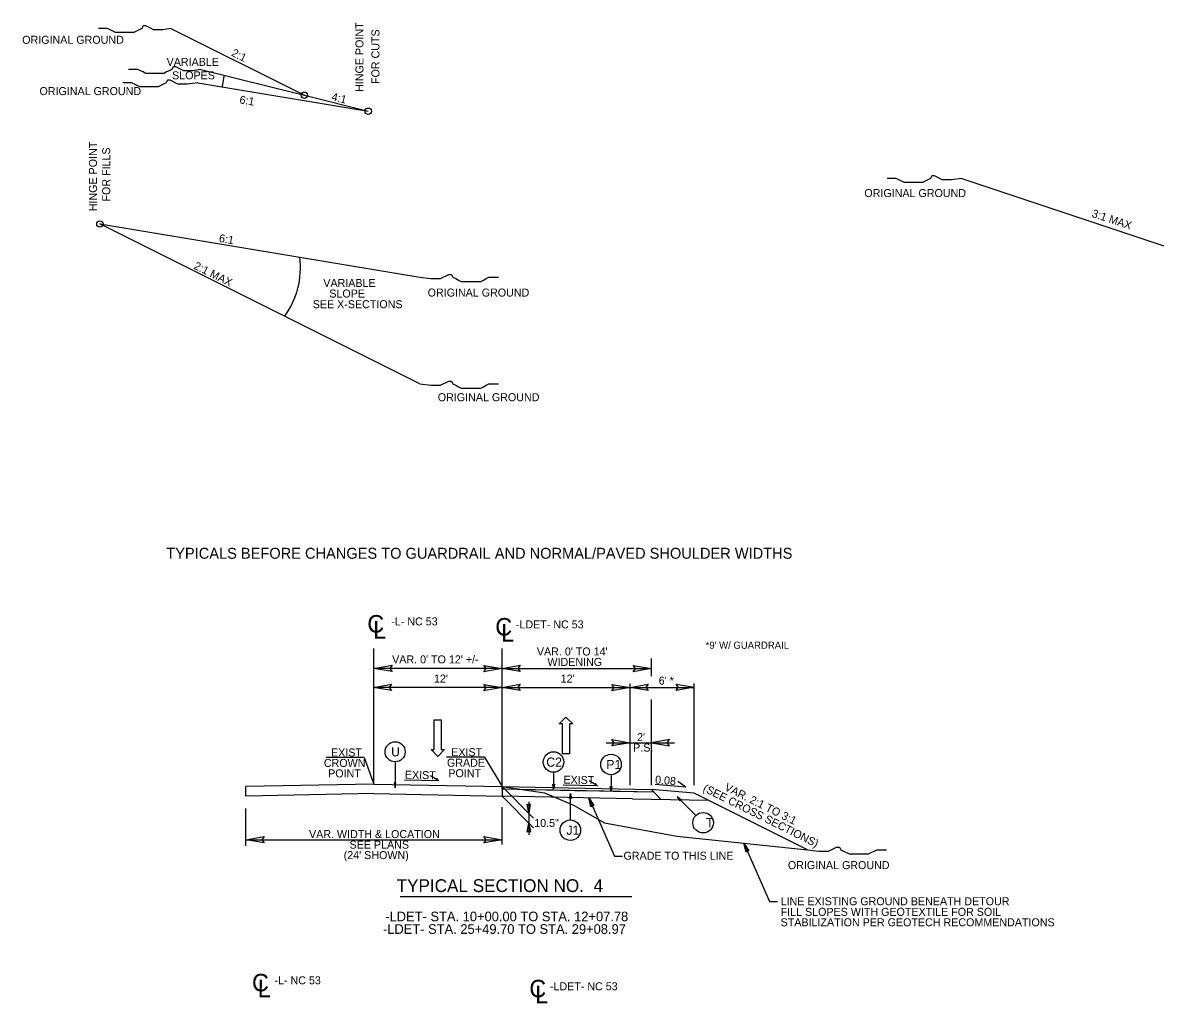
# Model space of a CAD drawing. Extents: x 1548135 to 1549339, y 868664 to 869085.
# Drawn here: x 1548321.3 to 1548427.5, y 868837.2 to 868929.2 of the extents above; entities that cross this region are included whole.
import ezdxf

# ---------------------------------------------------------------- set-up
doc = ezdxf.new("R2010")
doc.units = 0
for name, color, linetype in [('P_RDY_TC_Pvmt_Asphalt_Base_Course', 7, 'Continuous'), ('Prop Dimension', 7, 'Continuous'), ('Prop Terminator CELL', 7, 'Continuous'), ('Sheet_Data_Field_CELL', 7, 'Continuous'), ('Sheet_Plan', 7, 'Continuous'), ('Sheet_Title_Block_Text', 7, 'Continuous'), ('Typical Grade Point Symbol CELL', 7, 'Continuous'), ('Typical Hinge Slope Arterial CELL', 7, 'Continuous'), ('Typical Hinge Slope Interstate CELL', 7, 'Continuous'), ('Typical Pavement Slope Information CELL', 7, 'Continuous'), ('Typical Shoulder Slope CELL', 7, 'Continuous'), ('Typical Shoulder Slope Information CELL', 7, 'Continuous'), ('Typical Terminator CELL', 7, 'Continuous'), ('Typical Text Centerline CELL', 7, 'Continuous'), ('Typical Text General CELL', 7, 'Continuous'), ('Typical Text Grade Point CELL', 7, 'Continuous'), ('z - Construction', 7, 'Continuous')]:
    doc.layers.add(name, color=color, linetype=linetype)

msp = doc.modelspace()

# ---------------------------------------------------------------- linework, layer by layer
at = {"layer": 'P_RDY_TC_Pvmt_Asphalt_Base_Course'}
for points in [[(1548355.96, 868868.31), (1548354.27, 868868.6), (1548355.97, 868868.9), (1548355.75, 868868.6)], [(1548364.58, 868868.89), (1548366.27, 868868.6), (1548364.58, 868868.3), (1548364.79, 868868.6)], [(1548367.96, 868868.31), (1548366.27, 868868.6), (1548367.97, 868868.9), (1548367.75, 868868.6)], [(1548378.58, 868868.89), (1548380.27, 868868.6), (1548378.58, 868868.3), (1548378.79, 868868.6)], [(1548355.9, 868866.53), (1548354.21, 868866.82), (1548355.91, 868867.12), (1548355.69, 868866.82)], [(1548364.58, 868867.11), (1548366.27, 868866.82), (1548364.58, 868866.52), (1548364.79, 868866.82)], [(1548367.96, 868866.53), (1548366.27, 868866.82), (1548367.97, 868867.12), (1548367.75, 868866.82)], [(1548376.58, 868867.11), (1548378.27, 868866.82), (1548376.58, 868866.52), (1548376.79, 868866.82)], [(1548379.96, 868866.53), (1548378.27, 868866.82), (1548379.97, 868867.12), (1548379.75, 868866.82)], [(1548382.6, 868867.13), (1548384.28, 868866.84), (1548382.59, 868866.54), (1548382.8, 868866.84)], [(1548376.58, 868861.94), (1548378.27, 868861.64), (1548376.58, 868861.34), (1548376.79, 868861.64)], [(1548381.96, 868861.94), (1548380.27, 868861.64), (1548381.97, 868861.34), (1548381.75, 868861.64)], [(1548343.96, 868852.26), (1548342.27, 868852.55), (1548343.97, 868852.85), (1548343.75, 868852.55)], [(1548364.58, 868852.84), (1548366.27, 868852.55), (1548364.58, 868852.25), (1548364.79, 868852.55)]]:
    msp.add_lwpolyline(points, close=True, dxfattribs=at)
at = {"layer": 'Prop Dimension'}
for p, q in [((1548358.56, 868895.28), (1548328.57, 868910.28)), ((1548394.92, 868851.6), (1548384.28, 868856.92))]:
    msp.add_line(p, q, dxfattribs=at)
for points in [[(1548358.56, 868905.28), (1548359.6, 868905.15), (1548359.86, 868905.15), (1548360.25, 868905.15), (1548360.51, 868905.15), (1548360.77, 868905.28), (1548361.03, 868905.41), (1548361.29, 868905.54), (1548361.54, 868905.54), (1548361.67, 868905.28), (1548361.93, 868905.15), (1548362.19, 868905.02), (1548362.45, 868904.89), (1548362.71, 868904.89), (1548362.97, 868904.89), (1548363.23, 868904.89), (1548363.49, 868904.89), (1548363.75, 868904.89), (1548364.01, 868904.89), (1548364.27, 868904.89), (1548364.53, 868905.02), (1548364.79, 868905.15), (1548365.05, 868905.28), (1548365.44, 868905.28), (1548365.69, 868905.28), (1548365.95, 868905.28)], [(1548358.56, 868895.28), (1548359.6, 868895.15), (1548359.86, 868895.15), (1548360.25, 868895.15), (1548360.51, 868895.15), (1548360.77, 868895.28), (1548361.03, 868895.41), (1548361.29, 868895.54), (1548361.54, 868895.54), (1548361.67, 868895.28), (1548361.93, 868895.15), (1548362.19, 868895.02), (1548362.45, 868894.89), (1548362.71, 868894.89), (1548362.97, 868894.89), (1548363.23, 868894.89), (1548363.49, 868894.89), (1548363.75, 868894.89), (1548364.01, 868894.89), (1548364.27, 868894.89), (1548364.53, 868895.02), (1548364.79, 868895.15), (1548365.05, 868895.28), (1548365.44, 868895.28), (1548365.69, 868895.28), (1548365.95, 868895.28)], [(1548394.92, 868851.6), (1548395.96, 868851.47), (1548396.22, 868851.47), (1548396.61, 868851.47), (1548396.87, 868851.47), (1548397.13, 868851.6), (1548397.39, 868851.73), (1548397.64, 868851.86), (1548397.9, 868851.86), (1548398.03, 868851.6), (1548398.29, 868851.47), (1548398.55, 868851.34), (1548398.81, 868851.21), (1548399.07, 868851.21), (1548399.33, 868851.21), (1548399.59, 868851.21), (1548399.85, 868851.21), (1548400.11, 868851.21), (1548400.37, 868851.21), (1548400.63, 868851.21), (1548400.89, 868851.34), (1548401.15, 868851.47), (1548401.41, 868851.6), (1548401.8, 868851.6), (1548402.05, 868851.6), (1548402.31, 868851.6)]]:
    msp.add_lwpolyline(points, dxfattribs=at)
at = {"layer": 'Prop Terminator CELL'}
msp.add_lwpolyline([(1548366.27, 868857.53), (1548380.27, 868857.24), (1548380.52, 868857), (1548376.7, 868857.07), (1548375.4, 868857.1), (1548373.11, 868857.14), (1548366.27, 868857.28), (1548366.27, 868857.28)], close=True, dxfattribs=at)
at = {"layer": 'Sheet_Data_Field_CELL'}
for p, q in [((1548335.22, 868928.61), (1548347.74, 868922.35)), ((1548338.04, 868924.77), (1548347.74, 868922.35)), ((1548337.74, 868923.52), (1548353.73, 868920.85)), ((1548347.74, 868922.35), (1548353.73, 868920.85)), ((1548409.39, 868914.54), (1548438.24, 868904.93)), ((1548328.57, 868910.28), (1548358.56, 868905.28))]:
    msp.add_line(p, q, dxfattribs=at)
for points in [[(1548335.22, 868928.61), (1548334.48, 868928.49), (1548334.23, 868928.49), (1548333.86, 868928.49), (1548333.61, 868928.49), (1548333.37, 868928.61), (1548333.12, 868928.73), (1548332.87, 868928.86), (1548332.63, 868928.86), (1548332.5, 868928.61), (1548332.26, 868928.49), (1548332.01, 868928.36), (1548331.77, 868928.24), (1548331.52, 868928.24), (1548331.27, 868928.24), (1548331.03, 868928.24), (1548330.78, 868928.24), (1548330.53, 868928.24), (1548330.29, 868928.24), (1548330.04, 868928.24), (1548329.79, 868928.36), (1548329.55, 868928.49), (1548329.3, 868928.61), (1548328.93, 868928.61), (1548328.69, 868928.61), (1548328.44, 868928.61)], [(1548338.04, 868924.77), (1548337.3, 868924.65), (1548337.05, 868924.65), (1548336.68, 868924.65), (1548336.43, 868924.65), (1548336.19, 868924.77), (1548335.94, 868924.9), (1548335.7, 868925.02), (1548335.45, 868925.02), (1548335.33, 868924.77), (1548335.08, 868924.65), (1548334.83, 868924.53), (1548334.59, 868924.4), (1548334.34, 868924.4), (1548334.09, 868924.4), (1548333.85, 868924.4), (1548333.6, 868924.4), (1548333.35, 868924.4), (1548333.11, 868924.4), (1548332.86, 868924.4), (1548332.62, 868924.53), (1548332.37, 868924.65), (1548332.12, 868924.77), (1548331.75, 868924.77), (1548331.51, 868924.77), (1548331.26, 868924.77)], [(1548337.74, 868923.52), (1548336.75, 868923.39), (1548336.51, 868923.39), (1548336.14, 868923.39), (1548335.89, 868923.39), (1548335.64, 868923.52), (1548335.4, 868923.64), (1548335.15, 868923.76), (1548334.9, 868923.76), (1548334.78, 868923.52), (1548334.53, 868923.39), (1548334.29, 868923.27), (1548334.04, 868923.15), (1548333.79, 868923.15), (1548333.55, 868923.15), (1548333.3, 868923.15), (1548333.06, 868923.15), (1548332.81, 868923.15), (1548332.56, 868923.15), (1548332.32, 868923.15), (1548332.07, 868923.27), (1548331.82, 868923.39), (1548331.58, 868923.52), (1548331.21, 868923.52), (1548330.96, 868923.52), (1548330.71, 868923.52)], [(1548409.39, 868914.54), (1548408.41, 868914.42), (1548408.16, 868914.42), (1548407.79, 868914.42), (1548407.54, 868914.42), (1548407.3, 868914.54), (1548407.05, 868914.67), (1548406.8, 868914.79), (1548406.56, 868914.79), (1548406.43, 868914.54), (1548406.19, 868914.42), (1548405.94, 868914.3), (1548405.69, 868914.17), (1548405.45, 868914.17), (1548405.2, 868914.17), (1548404.96, 868914.17), (1548404.71, 868914.17), (1548404.46, 868914.17), (1548404.22, 868914.17), (1548403.97, 868914.17), (1548403.72, 868914.3), (1548403.48, 868914.42), (1548403.23, 868914.54), (1548402.86, 868914.54), (1548402.61, 868914.54), (1548402.37, 868914.54)]]:
    msp.add_lwpolyline(points, dxfattribs=at)
for centre in [(1548347.74, 868922.35), (1548353.73, 868920.85), (1548328.57, 868910.28)]:
    msp.add_circle(centre, 0.297, dxfattribs=at)
for centre, start, end in [((1548347.74, 868922.35), 165.9637, 174.1897), ((1548339.64, 868906.21), 323.6378, 6.9738)]:
    msp.add_arc(centre, 7.74, start, end, dxfattribs=at)
at = {"layer": 'Sheet_Plan'}
msp.add_line((1548384.28, 868856.92), (1548380.27, 868857.25), dxfattribs=at)
at = {"layer": 'Typical Grade Point Symbol CELL'}
for p, q in [((1548354.27, 868857.81), (1548354.27, 868870.48)), ((1548366.27, 868857.53), (1548366.27, 868870.48)), ((1548380.27, 868867.88), (1548380.27, 868869.55)), ((1548366.27, 868868.6), (1548354.27, 868868.6)), ((1548366.27, 868868.6), (1548380.27, 868868.6)), ((1548354.27, 868858.2), (1548354.27, 868867.14)), ((1548366.27, 868866.82), (1548354.27, 868866.82)), ((1548366.27, 868866.82), (1548384.28, 868866.82)), ((1548378.27, 868857.65), (1548378.27, 868867.16)), ((1548378.27, 868857.65), (1548378.27, 868867.16)), ((1548384.28, 868857.67), (1548384.28, 868867.18)), ((1548380.27, 868857.65), (1548380.27, 868865.69)), ((1548376.02, 868861.64), (1548382.45, 868861.64))]:
    msp.add_line(p, q, dxfattribs=at)
at = {"layer": 'Typical Hinge Slope Arterial CELL'}
for p, q in [((1548353.35, 868860.26), (1548349.79, 868860.26)), ((1548364.62, 868860.28), (1548361.06, 868860.28))]:
    msp.add_line(p, q, dxfattribs=at)
at = {"layer": 'Typical Hinge Slope Interstate CELL'}
for p, q in [((1548356.25, 868859.84), (1548356.25, 868857.41)), ((1548371.1, 868858.86), (1548371.1, 868857.3)), ((1548354.27, 868857.77), (1548342.27, 868857.53)), ((1548354.27, 868857.77), (1548366.27, 868857.53)), ((1548376.49, 868858.64), (1548376.49, 868857.08)), ((1548342.27, 868856.63), (1548342.27, 868857.53)), ((1548354.27, 868856.87), (1548342.27, 868856.63)), ((1548354.27, 868856.87), (1548366.27, 868856.63)), ((1548369.22, 868854.58), (1548366.27, 868857.53)), ((1548366.27, 868857.53), (1548366.27, 868856.63)), ((1548380.52, 868857), (1548366.27, 868857.28)), ((1548378.49, 868856.39), (1548366.27, 868856.63)), ((1548369.22, 868853.67), (1548366.27, 868856.62)), ((1548372.68, 868854.41), (1548372.68, 868856.89)), ((1548368.78, 868856.1), (1548368.78, 868853.01)), ((1548384.44, 868854.82), (1548382.68, 868856.57))]:
    msp.add_line(p, q, dxfattribs=at)
for points in [[(1548356.17, 868857.87), (1548356.25, 868857.41), (1548356.33, 868857.87), (1548356.25, 868857.81)], [(1548371.18, 868857.77), (1548371.1, 868857.3), (1548371.02, 868857.77), (1548371.1, 868857.71)], [(1548372.6, 868856.42), (1548372.68, 868856.89), (1548372.77, 868856.42), (1548372.68, 868856.48)], [(1548376.57, 868857.55), (1548376.49, 868857.08), (1548376.41, 868857.55), (1548376.49, 868857.49)], [(1548368.92, 868855.87), (1548368.78, 868855.03), (1548368.63, 868855.87), (1548368.78, 868855.77)], [(1548374.61, 868855.64), (1548374.4, 868856.47), (1548374.88, 868855.75), (1548374.7, 868855.79)], [(1548383.07, 868856.3), (1548382.68, 868856.57), (1548382.95, 868856.18), (1548382.97, 868856.28)], [(1548368.63, 868853.27), (1548368.78, 868854.11), (1548368.93, 868853.27), (1548368.78, 868853.37)], [(1548389.15, 868851.39), (1548388.94, 868852.22), (1548389.42, 868851.5), (1548389.24, 868851.54)]]:
    msp.add_lwpolyline(points, close=True, dxfattribs=at)
for points in [[(1548366.27, 868857.53), (1548370.25, 868856.95), (1548372.98, 868855.8), (1548375.89, 868854.12), (1548382.67, 868852.87), (1548394.92, 868851.6)], [(1548374.4, 868856.47), (1548376.82, 868851), (1548377.57, 868851)], [(1548388.94, 868852.22), (1548391.36, 868846.75), (1548392.11, 868846.75)]]:
    msp.add_lwpolyline(points, dxfattribs=at)
for centre, radius in [((1548356.25, 868860.79), 0.942), ((1548371.1, 868859.83), 0.962), ((1548376.49, 868859.6), 0.962), ((1548385.12, 868854.14), 0.962), ((1548372.68, 868853.44), 0.962)]:
    msp.add_circle(centre, radius, dxfattribs=at)
at = {"layer": 'Typical Pavement Slope Information CELL'}
for p, q in [((1548360.35, 868858.07), (1548357.12, 868858.14)), ((1548360.35, 868858.07), (1548359.57, 868858.54)), ((1548375.22, 868857.61), (1548371.99, 868857.67)), ((1548375.22, 868857.61), (1548374.43, 868858.08)), ((1548383.51, 868857.48), (1548380.62, 868857.72)), ((1548383.51, 868857.48), (1548382.75, 868858))]:
    msp.add_line(p, q, dxfattribs=at)
at = {"layer": 'Typical Shoulder Slope CELL'}
for p, q in [((1548353.35, 868860.26), (1548354.27, 868857.77)), ((1548364.62, 868860.28), (1548366.27, 868857.53))]:
    msp.add_line(p, q, dxfattribs=at)
at = {"layer": 'Typical Shoulder Slope Information CELL'}
for p, q in [((1548371.64, 868863.4), (1548372.26, 868864.03)), ((1548372.26, 868864.03), (1548372.9, 868863.4)), ((1548359.92, 868860.99), (1548359.92, 868863.79)), ((1548359.92, 868863.79), (1548360.58, 868863.79)), ((1548360.58, 868863.79), (1548360.58, 868860.99)), ((1548371.94, 868863.4), (1548371.64, 868863.4)), ((1548371.94, 868860.6), (1548371.94, 868863.4)), ((1548372.9, 868863.4), (1548372.6, 868863.4)), ((1548372.6, 868863.4), (1548372.6, 868860.6)), ((1548360.26, 868860.36), (1548359.62, 868860.99)), ((1548359.62, 868860.99), (1548359.92, 868860.99)), ((1548360.88, 868860.99), (1548360.26, 868860.36)), ((1548360.58, 868860.99), (1548360.88, 868860.99)), ((1548372.6, 868860.6), (1548371.94, 868860.6))]:
    msp.add_line(p, q, dxfattribs=at)
at = {"layer": 'Typical Terminator CELL'}
for p, q in [((1548366.27, 868852.09), (1548366.27, 868855.6)), ((1548342.27, 868851.98), (1548342.27, 868855.48)), ((1548342.27, 868852.55), (1548366.27, 868852.55)), ((1548356.72, 868847.23), (1548378.44, 868847.23))]:
    msp.add_line(p, q, dxfattribs=at)
at = {"layer": 'Typical Text Grade Point CELL'}
for p, q in [((1548366.27, 868857.53), (1548380.27, 868857.25)), ((1548380.27, 868857.25), (1548381.17, 868856.33)), ((1548378.49, 868856.39), (1548385.63, 868856.24))]:
    msp.add_line(p, q, dxfattribs=at)

# ---------------------------------------------------------------- texts
at = {"layer": 'Prop Dimension'}
msp.add_text('2:1 MAX', height=0.75, rotation=333.434, dxfattribs=at).set_placement((1548337.31, 868906.11))
at = {"layer": 'Sheet_Data_Field_CELL'}
for s, rotation, p in [('HINGE POINT ', 90, (1548353.28, 868922.66)), ('FOR CUTS', 90, (1548354.78, 868923.4)), ('2:1', 333.4349, (1548340.84, 868926.08)), ('4:1', 345.9638, (1548350.24, 868921.89)), ('6:1', 350.5365, (1548341.62, 868921.59)), ('HINGE POINT ', 90, (1548328.3, 868911.47)), ('FOR FILLS', 90, (1548329.54, 868912.38)), ('3:1 MAX', 341.565, (1548421.5, 868910.96)), ('6:1', 350.5365, (1548339.7, 868908.6)), ('(SEE CROSS SECTIONS)', 333.434, (1548385.04, 868857.13)), ('VAR. 2:1 TO 3:1', 333.434, (1548387.06, 868857.22))]:
    msp.add_text(s, height=0.75, rotation=rotation, dxfattribs=at).set_placement(p)
for s, p in [('ORIGINAL GROUND', (1548321.29, 868927.17)), ('VARIABLE ', (1548334.83, 868925.1)), ('SLOPES', (1548335.34, 868923.84)), ('ORIGINAL GROUND', (1548322.91, 868922.36)), ('ORIGINAL GROUND', (1548400.24, 868912.8)), ('VARIABLE ', (1548349.52, 868904.37)), ('SLOPE', (1548350.08, 868903.38)), ('ORIGINAL GROUND', (1548359.3, 868903.47)), ('SEE X-SECTIONS', (1548348.53, 868902.38)), ('ORIGINAL GROUND', (1548360.25, 868893.66)), ('ORIGINAL GROUND', (1548393.07, 868849.79))]:
    msp.add_text(s, height=0.75, dxfattribs=at).set_placement(p)
at = {"layer": 'Sheet_Title_Block_Text'}
for p in [(1548353.64, 868871.97), (1548365.64, 868871.69), (1548342.83, 868838.33), (1548368.83, 868837.77)]:
    msp.add_text('C', height=1.64, dxfattribs=at).set_placement(p)
for p in [(1548354.19, 868871.41), (1548366.19, 868871.13), (1548343.37, 868837.77), (1548369.37, 868837.21)]:
    msp.add_text('L', height=1.64, rotation=359.9469, dxfattribs=at).set_placement(p)
at = {"layer": 'Typical Hinge Slope Arterial CELL'}
msp.add_text('TYPICAL SECTION NO.  4', height=1.2, dxfattribs=at).set_placement((1548356.39, 868847.64))
at = {"layer": 'Typical Hinge Slope Interstate CELL'}
for s, height, p in [('TYPICALS BEFORE CHANGES TO GUARDRAIL AND NORMAL/PAVED SHOULDER WIDTHS', 1.0232, (1548334.8, 868878.89)), ('-L- NC 53', 0.75, (1548355.89, 868872.64)), ('-LDET- NC 53', 0.75, (1548367.57, 868872.36)), ('U', 0.844, (1548355.88, 868860.36)), ('C2', 0.861, (1548370.42, 868859.39)), ('P1', 0.861, (1548376.04, 868859.17)), ('10.5"', 0.75, (1548369.29, 868853.74)), ('T', 0.861, (1548385.4, 868853.71)), ('J1', 0.861, (1548372.31, 868853.01)), ('GRADE TO THIS LINE', 0.75, (1548377.66, 868850.67)), ('LINE EXISTING GROUND BENEATH DETOUR', 0.75, (1548392.39, 868846.4)), ('FILL SLOPES WITH GEOTEXTILE FOR SOIL', 0.75, (1548392.39, 868845.41)), ('STABILIZATION PER GEOTECH RECOMMENDATIONS', 0.75, (1548392.39, 868844.43)), ('-L- NC 53', 0.75, (1548344.94, 868838.99)), ('-LDET- NC 53', 0.75, (1548370.76, 868838.43))]:
    msp.add_text(s, height=height, dxfattribs=at).set_placement(p)
at = {"layer": 'Typical Pavement Slope Information CELL'}
for p in [(1548357.16, 868858.27), (1548372.02, 868857.81)]:
    msp.add_text('EXIST.', height=0.75, rotation=358.8544, dxfattribs=at).set_placement(p)
at = {"layer": 'Typical Shoulder Slope CELL'}
for s, p in [("VAR. 0' TO 14' ", (1548369.54, 868869.82)), ("VAR. 0' TO 12' +/-", (1548355.97, 868869.08)), ('WIDENING', (1548370.53, 868868.84)), ("12'", (1548359.89, 868867.28)), ("12'", (1548371.77, 868867.28)), ("6' *", (1548380.96, 868867.09)), ('EXIST', (1548350.24, 868860.35)), ('EXIST', (1548361.51, 868860.38)), ('CROWN', (1548349.57, 868859.37)), ('GRADE', (1548361.11, 868859.39)), ('POINT', (1548349.97, 868858.39)), ('POINT', (1548361.24, 868858.41)), ('VAR. WIDTH & LOCATION', (1548348.18, 868852.7)), ('SEE PLANS', (1548351.98, 868851.71)), ("(24' SHOWN)", (1548351.43, 868850.73))]:
    msp.add_text(s, height=0.75, dxfattribs=at).set_placement(p)
at = {"layer": 'Typical Text Centerline CELL'}
for s, p in [("2'", (1548378.93, 868861.79)), ('P.S.', (1548378.56, 868860.81))]:
    msp.add_text(s, height=0.75, dxfattribs=at).set_placement(p)
at = {"layer": 'Typical Text General CELL'}
for s, height, p in [("*9' W/ GUARDRAIL", 0.6682, (1548385.36, 868870.45)), ('-LDET- STA. 10+00.00 TO STA. 12+07.78', 0.9039, (1548355.33, 868844.9)), ('-LDET- STA. 25+49.70 TO STA. 29+08.97', 0.9039, (1548355.11, 868843.72))]:
    msp.add_text(s, height=height, dxfattribs=at).set_placement(p)
at = {"layer": 'z - Construction'}
msp.add_text('0.08', height=0.75, rotation=355.2385, dxfattribs=at).set_placement((1548380.6, 868857.82))

doc.saveas('drawing.dxf')
